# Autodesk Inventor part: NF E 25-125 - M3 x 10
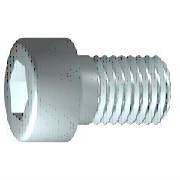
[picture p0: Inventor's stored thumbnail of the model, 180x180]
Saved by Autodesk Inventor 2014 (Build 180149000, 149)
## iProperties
IsCustomPart: 0
Created: 2007-03
Part Number: NF E 25-125 - M3 x 10
Material: Steel, Mild
Description: Slotted cheese head - Product grade A - Symbol C S
Document SubType Name: Modeling
Standard: NF E 25-125
Designer: Autodesk, Inc.
Standards Organization: AFNOR
Language: en-US
Size Designation: M3 x 10
Categories: <MemberInstance><Categories><Category DisplayName="Fasteners" InternalName="e4da775c-781d-43d5-af7c-5136215cf5a6" Mnemonic="FSTN"><Category DisplayName="Bolts"
Density: 7.86 g/cm^3
Mass: 1.04096 g
Surface Area: 2.01851 cm^2
Volume: 0.132438 cm^3
Appearance: Steel
Author: Autodesk, Inc.
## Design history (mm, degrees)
sketch "Sketch1"
  geometry: L1 (-0.867, 0)-(10, 0); L2 (10, 0)-(10, 1.5); L3 (10, 1.5)-(1.25, 1.5); L4 (1.25, 1.5)-(0.943, 1.5); L5 (0.943, 1.5)-(0, 1.5); L6 (0, 1.5)-(0, 2.75); L7 (0, 2.75)-(-3, 2.75); L8 (-3, 2.75)-(-3, 1.443); L9 (-3, 1.443)-(-1.7, 1.443); L10 (-1.7, 1.443)-(-0.867, 0); L11 (-5.6, 0)-(12.6, 0) reference; L12 (0, -0.55)-(0, 3.3) reference; L13 (1.25, 1.5)-(0, 1.5)
  constraints: 22 end point, 6 parallel, 2 collinear, 2 perpendicular, 1 horizontal, 1 point on line
  dimensions: "d1" = 8.75 distance from line of L3.end L2 (= GEL); "d2" = 0.30683 distance of L4.end L3.end (computed from GAL); "d3" = 3 distance between parallel lines of L8 L6 (= KOH); "d4" = 1.3 distance of L8.end L9.end (= INTI); "d5" = 60 deg angle of L10 L1; "d6" = 3 diameter of L3 L1 (= GD); "d7" = 3 diameter of L5 L1 (= BDM); "d8" = 2.88675 diameter of L9 L1 (= 1.1547 x SW); "d9" = 5.5 diameter of L7 L1 (= KOD); "d26" = 10 distance between parallel lines of L12 L2 (= NLG)
revolve "Body" sketch "Sketch1" stored, may be unused: angle "d10" = 90 deg
sketch "Sketch2"
  geometry: L1 (0, -3.85)-(0, 3.85) reference; L2 (-3.85, 0)-(3.85, 0) reference; L3 (1.443, 0)-(0.722, -1.25); L4 (0.722, -1.25)-(-0.722, -1.25); L5 (-0.722, -1.25)-(-1.443, 0); L6 (-1.443, 0)-(-0.722, 1.25); L7 (-0.722, 1.25)-(0.722, 1.25); L8 (0.722, 1.25)-(1.443, 0); 2 further points
  constraints: 12 end point, 1 coincident, 1 horizontal alignment, 1 point on line, 12 other
extrude "Slot" join sketch "Sketch2" stored distance "d11" = 10; taper "d12" = 0 deg
workplane "Work Plane1"
fillet "Fillet2" dims "d30" = 0.1 (= R)
body "Solid1"
fillet "Fillet1" dims "d17" = 0.3 (= RR)
feature "Thread" dims "d13" = 8.75 (= GEL), "d14" = 0
chamfer "Chamfer1" distance "d15" = 0.30673 (= -0.5 x SPD + 0.5 x GD); stored, may be unused: second distance "d16" = 0.30673 (= GUL), angle "d27" = 45 deg
other parameters: "GD" = 3 (= NND) [user parameter; used in 2 equation terms], "NLG" = 10 [user parameter; used in 1 equation term], "GEL" = 8.75 [user parameter; used in 2 equation terms], "KOD" = 5.5 [user parameter; used in 1 equation term], "KOH" = 3 (= NND) [user parameter; used in 1 equation term], "INTI" = 1.3 [user parameter; used in 1 equation term], "GAL" = 0.30673 (= 0.61345 x PTC) [user parameter; used in 1 equation term], "GUL" = 0.30673 (= 0.61345 x PTC) [user parameter; used in 1 equation term], "BDM" = 3 (= NND) [user parameter; used in 1 equation term], "SW" = 2.5 [user parameter; used in 2 equation terms], "RR" = 0.3 [user parameter; used in 1 equation term], "SPD" = 2.38655 (= NND - 1.2269 x PTC) [user parameter; used in 1 equation term], "d19" = 0, "d28" = 0, "d29" = 0, "R" = 0.1 [user parameter; used in 1 equation term], "TOA" = 30 deg [user parameter], "GD1" = 2.38655 (= THREADDIA - 1.2269 x PTC) [user parameter], "THREADDIA" = 3 [user parameter; used in 1 equation term], "FAWI" = 45 deg [user parameter], "PTC" = 0.5 [user parameter; used in 5 equation terms], "NND" = 3 [user parameter; used in 4 equation terms], "E0" = 2.8875 (= 1.155 x SW) [user parameter]
